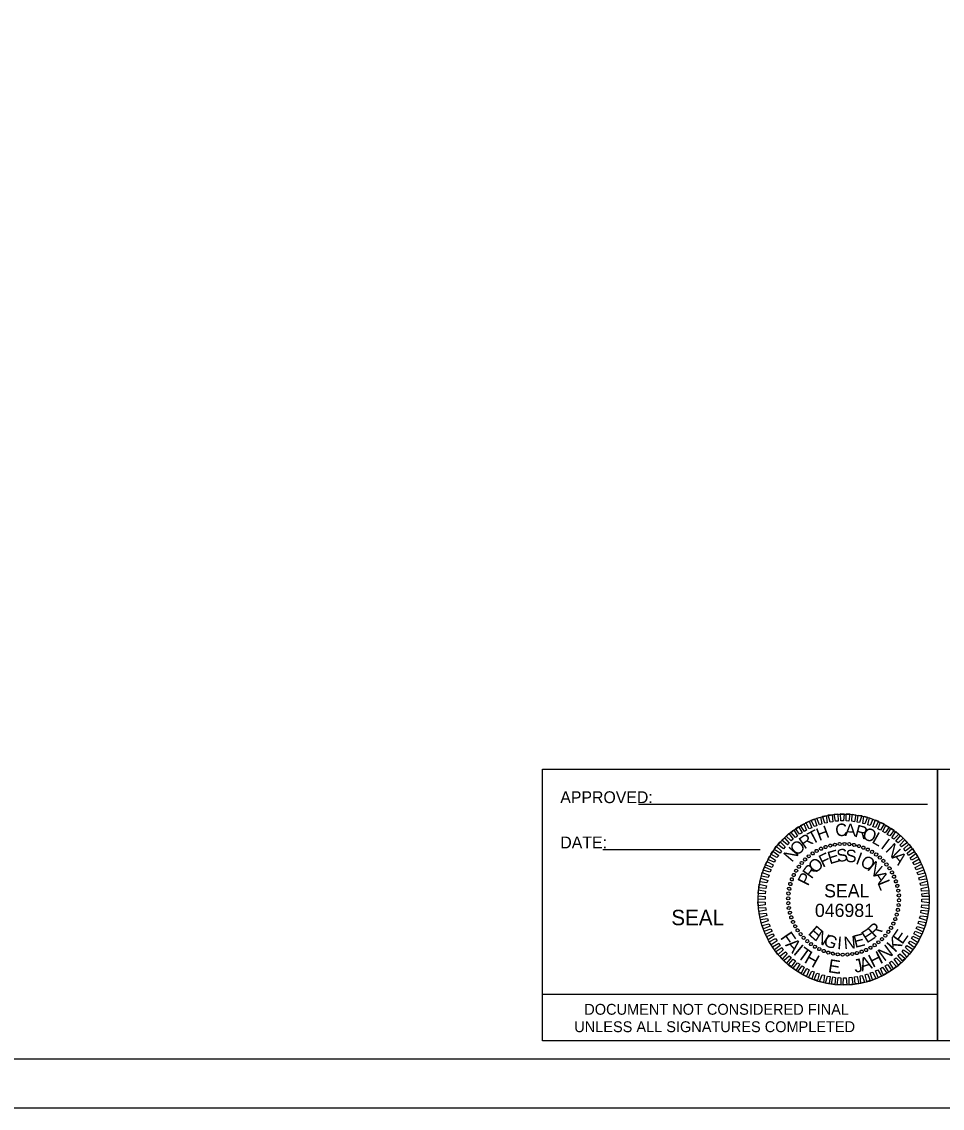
# Model space of a CAD drawing. Extents: x -0.1 to 33.8, y -19.9 to 2.3.
# Drawn here: x 16.81 to 26.19, y -19.85 to -8.8 of the extents above; entities that cross this region are included whole.
import ezdxf

# ---------------------------------------------------------------- set-up
doc = ezdxf.new("R2010")
doc.units = 0
for name, color, linetype in [('DEV PRELIMINARY STAMP CELL', 7, 'Continuous'), ('GSBWFILL', 7, 'Continuous'), ('GSOUTLINE', 7, 'Continuous'), ('Sheet PE Seal CELL', 7, 'Continuous'), ('Sheet Sticker Exception Certification CELL', 7, 'Continuous')]:
    doc.layers.add(name, color=color, linetype=linetype)

msp = doc.modelspace()

# ---------------------------------------------------------------- linework, layer by layer
at = {"layer": 'GSBWFILL'}
for p, q in [((23.093, -16.758), (26.034, -16.758)), ((26.138, -16.875), (26.138, -19.166)), ((22.729, -17.222), (24.333, -17.222))]:
    msp.add_line(p, q, dxfattribs=at)
for points in [[(33.276, 1.754), (3.126, 1.754), (3.126, -19.351), (33.276, -19.351)], [(22.117, -16.402), (26.138, -16.402), (26.138, -19.166), (22.117, -19.166)], [(26.138, -16.402), (28.429, -16.402), (28.429, -19.166), (26.138, -19.166)]]:
    msp.add_lwpolyline(points, close=True, dxfattribs=at)
msp.add_circle((25.181, -17.731), 0.871, dxfattribs=at)
at = {"layer": 'GSOUTLINE'}
msp.add_lwpolyline([(-0.15, 2.257), (33.779, 2.257), (33.779, -19.853), (-0.15, -19.853)], close=True, dxfattribs=at)
at = {"layer": 'Sheet PE Seal CELL'}
for p, q in [((24.908, -17.234), (24.908, -17.234)), ((24.951, -17.212), (24.951, -17.212)), ((24.996, -17.194), (24.996, -17.194)), ((25.043, -17.18), (25.043, -17.18)), ((25.093, -17.171), (25.093, -17.171)), ((25.141, -17.165), (25.141, -17.165)), ((25.191, -17.164), (25.191, -17.164)), ((25.24, -17.167), (25.24, -17.167)), ((25.288, -17.175), (25.288, -17.175)), ((25.335, -17.185), (25.335, -17.185)), ((25.383, -17.201), (25.383, -17.201)), ((25.428, -17.221), (25.428, -17.221)), ((25.471, -17.243), (25.471, -17.243)), ((24.788, -17.322), (24.788, -17.322)), ((24.826, -17.288), (24.826, -17.288)), ((24.865, -17.26), (24.865, -17.26)), ((25.512, -17.271), (25.512, -17.271)), ((25.551, -17.302), (25.551, -17.302)), ((25.586, -17.335), (25.586, -17.335)), ((24.696, -17.436), (24.696, -17.436)), ((24.724, -17.396), (24.724, -17.396)), ((24.755, -17.357), (24.755, -17.357)), ((25.62, -17.372), (25.62, -17.372)), ((25.648, -17.412), (25.648, -17.412)), ((25.674, -17.454), (25.674, -17.454)), ((24.638, -17.572), (24.638, -17.572)), ((24.654, -17.525), (24.654, -17.525)), ((24.674, -17.48), (24.674, -17.48)), ((25.696, -17.498), (25.696, -17.498)), ((25.714, -17.543), (25.714, -17.543)), ((24.62, -17.668), (24.62, -17.668)), ((24.628, -17.62), (24.628, -17.62)), ((25.728, -17.59), (25.728, -17.59)), ((25.736, -17.64), (25.736, -17.64)), ((24.617, -17.717), (24.617, -17.717)), ((24.618, -17.767), (24.618, -17.767)), ((25.18, -17.727), (25.18, -17.727)), ((25.741, -17.787), (25.741, -17.787)), ((25.743, -17.688), (25.743, -17.688)), ((25.744, -17.737), (25.744, -17.737)), ((24.624, -17.815), (24.624, -17.815)), ((24.633, -17.864), (24.633, -17.864)), ((25.723, -17.882), (25.723, -17.882)), ((25.733, -17.835), (25.733, -17.835)), ((24.647, -17.912), (24.647, -17.912)), ((24.665, -17.957), (24.665, -17.957)), ((24.687, -18), (24.687, -18)), ((25.665, -18.018), (25.665, -18.018)), ((25.687, -17.975), (25.687, -17.975)), ((25.707, -17.93), (25.707, -17.93)), ((24.713, -18.043), (24.713, -18.043)), ((24.741, -18.082), (24.741, -18.082)), ((24.775, -18.119), (24.775, -18.119)), ((25.606, -18.098), (25.606, -18.098)), ((25.637, -18.059), (25.637, -18.059)), ((24.81, -18.153), (24.81, -18.153)), ((24.849, -18.183), (24.849, -18.183)), ((24.89, -18.212), (24.89, -18.212)), ((24.933, -18.234), (24.933, -18.234)), ((25.453, -18.22), (25.453, -18.22)), ((25.496, -18.195), (25.496, -18.195)), ((25.535, -18.167), (25.535, -18.167)), ((25.572, -18.133), (25.572, -18.133)), ((24.978, -18.254), (24.978, -18.254)), ((25.025, -18.27), (25.025, -18.27)), ((25.073, -18.28), (25.073, -18.28)), ((25.121, -18.288), (25.121, -18.288)), ((25.17, -18.291), (25.17, -18.291)), ((25.22, -18.29), (25.22, -18.29)), ((25.268, -18.283), (25.268, -18.283)), ((25.318, -18.274), (25.318, -18.274)), ((25.365, -18.261), (25.365, -18.261)), ((25.41, -18.243), (25.41, -18.243))]:
    msp.add_line(p, q, dxfattribs=at)
for points in [[(24.881, -16.986), (24.851, -16.921), (24.885, -16.907), (24.909, -16.979)], [(24.936, -16.968), (24.91, -16.901), (24.945, -16.891), (24.959, -16.96)], [(24.99, -16.953), (24.966, -16.883), (25.004, -16.875), (25.013, -16.948)], [(25.043, -16.941), (25.025, -16.869), (25.063, -16.866), (25.07, -16.938)], [(25.097, -16.934), (25.085, -16.862), (25.123, -16.858), (25.124, -16.931)], [(25.154, -16.929), (25.148, -16.856), (25.185, -16.857), (25.18, -16.93)], [(25.207, -16.93), (25.207, -16.857), (25.245, -16.858), (25.234, -16.931)], [(25.264, -16.933), (25.268, -16.86), (25.305, -16.867), (25.291, -16.938)], [(25.318, -16.942), (25.328, -16.87), (25.365, -16.876), (25.344, -16.946)], [(25.375, -16.955), (25.386, -16.882), (25.424, -16.891), (25.398, -16.96)], [(25.429, -16.969), (25.446, -16.9), (25.48, -16.911), (25.452, -16.977)], [(24.691, -17.098), (24.642, -17.044), (24.673, -17.021), (24.712, -17.084)], [(24.733, -17.065), (24.692, -17.007), (24.721, -16.986), (24.758, -17.051)], [(24.783, -17.037), (24.741, -16.976), (24.776, -16.958), (24.804, -17.023)], [(24.831, -17.01), (24.795, -16.947), (24.83, -16.931), (24.856, -17)], [(25.479, -16.989), (25.505, -16.919), (25.537, -16.932), (25.505, -16.997)], [(25.53, -17.011), (25.558, -16.944), (25.593, -16.96), (25.555, -17.023)], [(25.581, -17.037), (25.612, -16.973), (25.646, -16.992), (25.603, -17.05)], [(25.625, -17.067), (25.665, -17.002), (25.694, -17.025), (25.65, -17.08)], [(24.609, -17.173), (24.551, -17.126), (24.58, -17.101), (24.627, -17.155)], [(24.646, -17.133), (24.596, -17.084), (24.623, -17.057), (24.667, -17.117)], [(25.671, -17.101), (25.713, -17.039), (25.742, -17.064), (25.693, -17.116)], [(25.714, -17.135), (25.76, -17.077), (25.787, -17.104), (25.735, -17.152)], [(25.754, -17.175), (25.803, -17.122), (25.83, -17.149), (25.771, -17.193)], [(24.502, -17.303), (24.439, -17.269), (24.462, -17.238), (24.52, -17.283)], [(24.536, -17.258), (24.475, -17.22), (24.496, -17.187), (24.55, -17.237)], [(24.569, -17.215), (24.511, -17.171), (24.536, -17.142), (24.585, -17.195)], [(25.794, -17.215), (25.845, -17.165), (25.869, -17.195), (25.809, -17.238)], [(25.827, -17.259), (25.883, -17.212), (25.904, -17.244), (25.841, -17.28)], [(24.453, -17.403), (24.383, -17.377), (24.4, -17.342), (24.464, -17.378)], [(24.475, -17.351), (24.411, -17.323), (24.428, -17.288), (24.489, -17.33)], [(25.857, -17.305), (25.916, -17.262), (25.938, -17.296), (25.872, -17.328)], [(25.886, -17.354), (25.949, -17.315), (25.963, -17.35), (25.899, -17.376)], [(24.413, -17.506), (24.344, -17.492), (24.352, -17.454), (24.422, -17.483)], [(24.43, -17.452), (24.361, -17.432), (24.375, -17.397), (24.443, -17.429)], [(25.908, -17.403), (25.975, -17.369), (25.989, -17.405), (25.92, -17.427)], [(25.929, -17.456), (25.997, -17.426), (26.009, -17.461), (25.94, -17.479)], [(24.39, -17.617), (24.318, -17.611), (24.322, -17.572), (24.395, -17.59)], [(24.399, -17.56), (24.329, -17.551), (24.337, -17.513), (24.408, -17.536)], [(25.947, -17.509), (26.018, -17.484), (26.025, -17.521), (25.954, -17.533)], [(25.96, -17.563), (26.031, -17.542), (26.038, -17.58), (25.967, -17.587)], [(24.384, -17.671), (24.311, -17.669), (24.313, -17.632), (24.386, -17.644)], [(25.97, -17.617), (26.043, -17.602), (26.047, -17.64), (25.975, -17.644)], [(25.977, -17.671), (26.05, -17.662), (26.052, -17.7), (25.979, -17.698)], [(24.384, -17.784), (24.311, -17.793), (24.309, -17.754), (24.382, -17.757)], [(24.383, -17.727), (24.31, -17.731), (24.31, -17.693), (24.383, -17.7)], [(25.977, -17.784), (26.05, -17.786), (26.048, -17.823), (25.975, -17.811)], [(25.978, -17.727), (26.051, -17.724), (26.051, -17.762), (25.978, -17.754)], [(24.391, -17.837), (24.318, -17.853), (24.314, -17.815), (24.386, -17.811)], [(24.401, -17.891), (24.33, -17.913), (24.323, -17.875), (24.394, -17.868)], [(25.962, -17.895), (26.032, -17.904), (26.024, -17.942), (25.953, -17.918)], [(25.971, -17.837), (26.043, -17.844), (26.039, -17.882), (25.966, -17.864)], [(24.414, -17.945), (24.343, -17.971), (24.336, -17.934), (24.407, -17.922)], [(24.432, -17.999), (24.364, -18.028), (24.352, -17.994), (24.421, -17.976)], [(25.931, -18.003), (26, -18.023), (25.986, -18.058), (25.918, -18.026)], [(25.948, -17.949), (26.017, -17.963), (26.009, -18), (25.939, -17.972)], [(24.453, -18.052), (24.386, -18.086), (24.372, -18.05), (24.441, -18.027)], [(24.475, -18.1), (24.412, -18.14), (24.398, -18.105), (24.462, -18.079)], [(24.504, -18.15), (24.445, -18.192), (24.423, -18.159), (24.489, -18.127)], [(25.886, -18.104), (25.95, -18.132), (25.933, -18.167), (25.872, -18.125)], [(25.908, -18.052), (25.978, -18.078), (25.961, -18.113), (25.897, -18.077)], [(24.534, -18.196), (24.478, -18.243), (24.457, -18.21), (24.52, -18.174)], [(24.567, -18.24), (24.516, -18.29), (24.492, -18.26), (24.551, -18.217)], [(25.792, -18.24), (25.85, -18.283), (25.825, -18.313), (25.776, -18.26)], [(25.825, -18.197), (25.886, -18.235), (25.865, -18.268), (25.811, -18.218)], [(25.859, -18.152), (25.922, -18.186), (25.899, -18.217), (25.841, -18.172)], [(24.607, -18.28), (24.558, -18.333), (24.531, -18.306), (24.59, -18.262)], [(24.647, -18.319), (24.601, -18.378), (24.574, -18.351), (24.626, -18.302)], [(24.69, -18.354), (24.648, -18.416), (24.619, -18.391), (24.668, -18.338)], [(25.715, -18.322), (25.765, -18.371), (25.738, -18.398), (25.694, -18.337)], [(25.752, -18.282), (25.809, -18.328), (25.781, -18.354), (25.734, -18.3)], [(24.736, -18.388), (24.696, -18.453), (24.667, -18.429), (24.711, -18.374)], [(24.779, -18.418), (24.749, -18.482), (24.715, -18.463), (24.758, -18.405)], [(24.831, -18.444), (24.803, -18.51), (24.768, -18.495), (24.806, -18.432)], [(24.882, -18.465), (24.856, -18.536), (24.824, -18.523), (24.856, -18.457)], [(25.53, -18.445), (25.566, -18.508), (25.531, -18.524), (25.505, -18.455)], [(25.578, -18.418), (25.62, -18.479), (25.585, -18.497), (25.557, -18.432)], [(25.628, -18.39), (25.669, -18.447), (25.64, -18.469), (25.603, -18.404)], [(25.67, -18.356), (25.719, -18.41), (25.688, -18.434), (25.649, -18.371)], [(24.932, -18.486), (24.915, -18.555), (24.881, -18.544), (24.909, -18.478)], [(24.986, -18.5), (24.975, -18.573), (24.937, -18.564), (24.963, -18.495)], [(25.043, -18.513), (25.033, -18.584), (24.996, -18.579), (25.016, -18.509)], [(25.097, -18.522), (25.093, -18.595), (25.056, -18.588), (25.07, -18.517)], [(25.154, -18.525), (25.154, -18.598), (25.116, -18.597), (25.127, -18.524)], [(25.207, -18.526), (25.213, -18.599), (25.176, -18.598), (25.18, -18.525)], [(25.264, -18.52), (25.276, -18.592), (25.238, -18.597), (25.237, -18.524)], [(25.318, -18.514), (25.335, -18.586), (25.298, -18.589), (25.291, -18.517)], [(25.371, -18.501), (25.395, -18.572), (25.357, -18.58), (25.348, -18.507)], [(25.425, -18.487), (25.451, -18.554), (25.416, -18.564), (25.402, -18.495)], [(25.48, -18.469), (25.51, -18.534), (25.476, -18.547), (25.452, -18.475)]]:
    msp.add_lwpolyline(points, close=True, dxfattribs=at)
for centre, major_axis in [((24.865, -17.26), (-0.009, 0.0134)), ((24.907, -17.235), (-0.0078, 0.0141)), ((24.951, -17.213), (-0.0066, 0.0148)), ((24.997, -17.195), (-0.0053, 0.0153)), ((25.044, -17.181), (-0.0039, 0.0157)), ((25.092, -17.171), (-0.0025, 0.016)), ((25.141, -17.165), (-0.0011, 0.0161)), ((25.19, -17.164), (0.0003, 0.0162)), ((25.239, -17.167), (0.0017, 0.0161)), ((25.288, -17.174), (0.0031, 0.0159)), ((25.336, -17.186), (0.0045, 0.0155)), ((25.382, -17.201), (0.0058, 0.0151)), ((25.427, -17.221), (0.0071, 0.0145)), ((25.471, -17.244), (0.0083, 0.0139)), ((24.755, -17.358), (-0.0122, 0.0106)), ((24.789, -17.322), (-0.0112, 0.0116)), ((24.826, -17.29), (-0.0102, 0.0126)), ((25.512, -17.272), (0.0095, 0.0131)), ((25.55, -17.302), (0.0106, 0.0122)), ((25.586, -17.336), (0.0116, 0.0112)), ((25.618, -17.373), (0.0126, 0.0102)), ((24.674, -17.48), (-0.0145, 0.0071)), ((24.698, -17.437), (-0.0139, 0.0083)), ((24.725, -17.396), (-0.0131, 0.0095)), ((25.648, -17.412), (0.0134, 0.009)), ((25.673, -17.454), (0.0141, 0.0078)), ((24.639, -17.572), (-0.0155, 0.0045)), ((24.654, -17.525), (-0.0151, 0.0058)), ((25.695, -17.498), (0.0148, 0.0066)), ((25.713, -17.544), (0.0153, 0.0053)), ((25.727, -17.591), (0.0157, 0.0039)), ((24.62, -17.668), (-0.0161, 0.0017)), ((24.627, -17.62), (-0.0159, 0.0031)), ((25.737, -17.639), (0.016, 0.0025)), ((25.743, -17.688), (0.0161, 0.0011)), ((24.617, -17.718), (-0.0162, 0.0003)), ((24.618, -17.767), (-0.0161, -0.0011)), ((24.624, -17.816), (-0.016, -0.0025)), ((25.741, -17.786), (0.0161, -0.0017)), ((25.744, -17.737), (0.0162, -0.0003)), ((24.634, -17.864), (-0.0157, -0.0039)), ((24.648, -17.911), (-0.0153, -0.0053)), ((25.722, -17.883), (0.0155, -0.0045)), ((25.734, -17.835), (0.0159, -0.0031)), ((24.666, -17.957), (-0.0148, -0.0066)), ((24.688, -18.001), (-0.0141, -0.0078)), ((25.663, -18.018), (0.0139, -0.0083)), ((25.687, -17.974), (0.0145, -0.0071)), ((25.706, -17.929), (0.0151, -0.0058)), ((24.713, -18.042), (-0.0134, -0.009)), ((24.743, -18.082), (-0.0126, -0.0102)), ((24.775, -18.119), (-0.0116, -0.0112)), ((25.572, -18.133), (0.0112, -0.0116)), ((25.606, -18.097), (0.0122, -0.0106)), ((25.636, -18.059), (0.0131, -0.0095)), ((24.811, -18.153), (-0.0106, -0.0122)), ((24.849, -18.183), (-0.0095, -0.0131)), ((24.89, -18.21), (-0.0083, -0.0139)), ((24.934, -18.234), (-0.0071, -0.0145)), ((24.979, -18.253), (-0.0058, -0.0151)), ((25.41, -18.242), (0.0066, -0.0148)), ((25.454, -18.22), (0.0078, -0.0141)), ((25.496, -18.194), (0.009, -0.0134)), ((25.535, -18.165), (0.0102, -0.0126)), ((25.025, -18.269), (-0.0045, -0.0155)), ((25.073, -18.28), (-0.0031, -0.0159)), ((25.122, -18.288), (-0.0017, -0.0161)), ((25.171, -18.291), (-0.0003, -0.0162)), ((25.22, -18.289), (0.0011, -0.0161)), ((25.269, -18.284), (0.0025, -0.016)), ((25.317, -18.274), (0.0039, -0.0157)), ((25.364, -18.26), (0.0053, -0.0153))]:
    msp.add_ellipse(centre, major_axis=major_axis, ratio=0.999708, dxfattribs=at)
at = {"layer": 'Sheet Sticker Exception Certification CELL'}
for p, q in [((22.117, -19.166), (22.117, -18.694)), ((22.117, -18.694), (26.138, -18.694)), ((26.138, -18.694), (26.138, -19.166)), ((26.138, -19.166), (22.117, -19.166))]:
    msp.add_line(p, q, dxfattribs=at)

# ---------------------------------------------------------------- texts
at = {"layer": 'DEV PRELIMINARY STAMP CELL'}
msp.add_text('SEAL', height=0.157, dxfattribs=at).set_placement((23.427, -17.991))
at = {"layer": 'GSBWFILL'}
for s, p in [('APPROVED:  ', (22.297, -16.749)), ('DATE:  ', (22.297, -17.209))]:
    msp.add_text(s, height=0.1206, dxfattribs=at).set_placement(p)
at = {"layer": 'Sheet PE Seal CELL'}
for s, height, rotation, p in [('T', 0.127, 27.8198, (24.859, -17.173)), ('H', 0.127, 20.6195, (24.932, -17.135)), ('C', 0.127, 6.2199, (25.103, -17.091)), ('A', 0.127, 359.0203, (25.192, -17.084)), ('R', 0.127, 344.6211, (25.286, -17.088)), ('O', 0.127, 337.4212, (25.361, -17.105)), ('O', 0.127, 42.2217, (24.705, -17.292)), ('R', 0.127, 35.0205, (24.783, -17.222)), ('L', 0.127, 330.2209, (25.46, -17.147)), ('I', 0.127, 323.0201, (25.551, -17.201)), ('N', 0.127, 49.4235, (24.654, -17.357)), ('E', 0.127, 16.6111, (25.04, -17.372)), ('S', 0.127, 7.2556, (25.118, -17.349)), ('S', 0.127, 357.9004, (25.198, -17.348)), ('N', 0.127, 315.8189, (25.599, -17.235)), ('O', 0.127, 44.6812, (24.894, -17.472)), ('F', 0.127, 25.967, (24.968, -17.406)), ('I', 0.127, 339.1896, (25.295, -17.363)), ('O', 0.127, 329.8335, (25.34, -17.379)), ('N', 0.127, 320.4766, (25.415, -17.424)), ('A', 0.127, 308.6172, (25.666, -17.302)), ('P', 0.127, 63.3989, (24.819, -17.599)), ('R', 0.127, 54.0397, (24.855, -17.527)), ('A', 0.127, 301.7603, (25.479, -17.483)), ('SEAL', 0.1347, 360, (24.983, -17.708)), ('L', 0.127, 292.4009, (25.523, -17.56)), ('E', 0.127, 318.2769, (24.812, -18.079)), ('E', 0.127, 33.1241, (25.417, -18.179)), ('R', 0.127, 42.4814, (25.497, -18.126)), ('F', 0.135, 304.4142, (24.53, -18.117)), ('N', 0.127, 327.634, (24.879, -18.14)), ('G', 0.127, 336.9902, (24.965, -18.19)), ('I', 0.127, 355.7012, (25.112, -18.233)), ('N', 0.127, 5.0564, (25.187, -18.236)), ('E', 0.127, 14.4118, (25.298, -18.223)), ('K', 0.135, 47.2091, (25.705, -18.276)), ('E', 0.135, 55.493, (25.778, -18.194)), ('A', 0.135, 311.4309, (24.582, -18.194)), ('I', 0.135, 320.2712, (24.661, -18.28)), ('T', 0.135, 324.0731, (24.699, -18.313)), ('N', 0.135, 36.4833, (25.593, -18.364)), ('H', 0.135, 330.8733, (24.771, -18.366)), ('E', 0.135, 351.0577, (25.017, -18.468)), ('J', 0.135, 12.4012, (25.298, -18.477)), ('A', 0.135, 17.659, (25.366, -18.463)), ('H', 0.135, 26.4993, (25.477, -18.426)), ('.', 0.135, 358.167, (25.11, -18.483))]:
    msp.add_text(s, height=height, rotation=rotation, dxfattribs=at).set_placement(p)
msp.add_text('046981', height=0.1347, dxfattribs=at).set_placement((24.889, -17.907))
at = {"layer": 'Sheet Sticker Exception Certification CELL'}
for s, p in [('DOCUMENT NOT CONSIDERED FINAL', (22.541, -18.902)), ('UNLESS ALL SIGNATURES COMPLETED', (22.439, -19.079))]:
    msp.add_text(s, height=0.11055, dxfattribs=at).set_placement(p)

doc.saveas('drawing.dxf')
